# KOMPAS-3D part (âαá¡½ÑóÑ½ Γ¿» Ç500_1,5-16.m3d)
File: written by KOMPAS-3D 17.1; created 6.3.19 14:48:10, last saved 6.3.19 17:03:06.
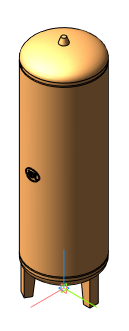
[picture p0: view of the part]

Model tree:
1. Операция без истории:1  (with: Сечение модели:1)

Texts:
  Гранлевел тип А100_1,5-16
  Гранлевел тип А150_1,5-16
  Гранлевел тип А220_1,5-16
  Гранлевел тип А350_1,5-16
  Гранлевел тип А500_1,5-16
  Гранлевел тип А700_1,5-16
  Гранлевел тип А900_1,5-16
  Гранлевел тип А1000_1,5-16
  Гранлевел тип А1400_1,5-16
  Точка начала. Х
  Точка начала. Y
  Точка начала. Z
